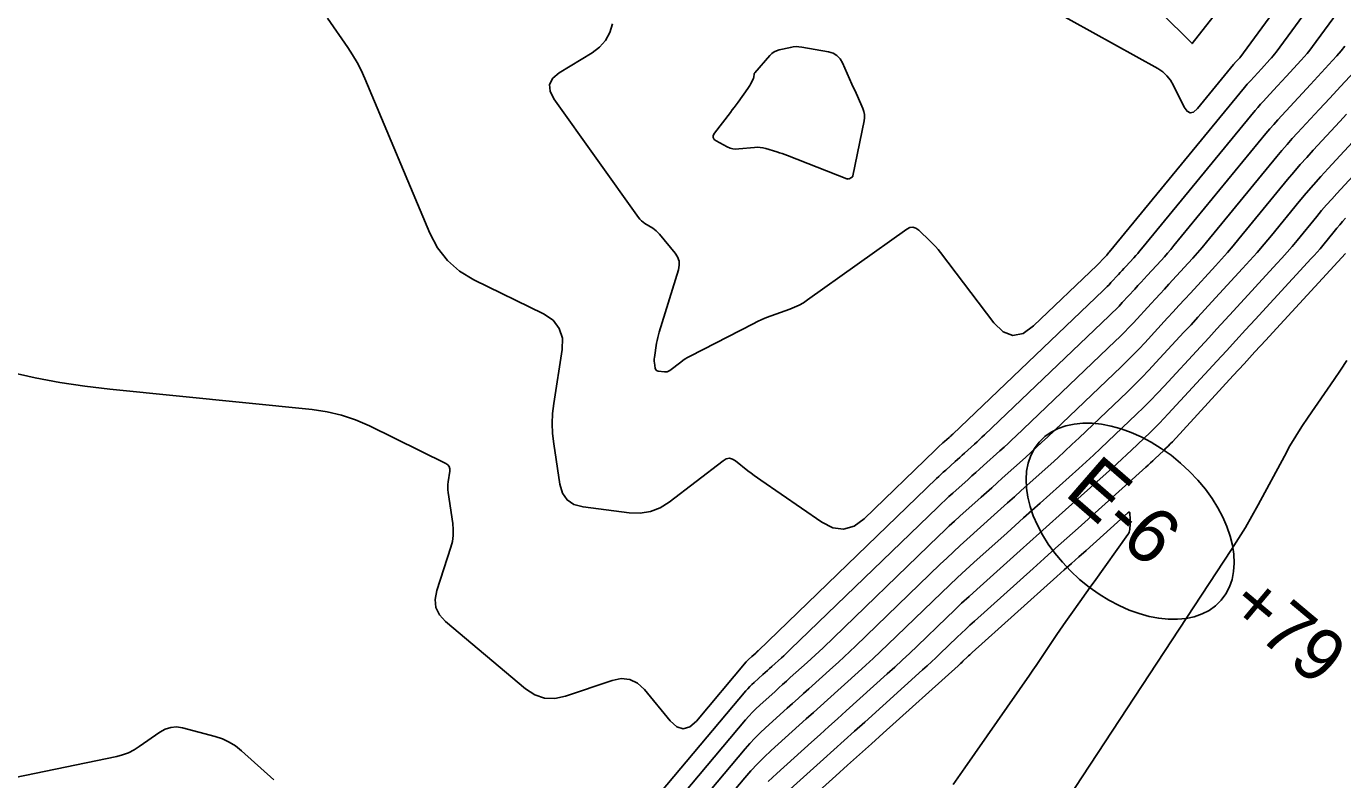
# Model space of a CAD drawing. Extents: x 1005228 to 1008882, y 1883389 to 1885754.
# Drawn here: x 1007592.2 to 1007741.8, y 1884616.1 to 1884701.7 of the extents above; entities that cross this region are included whole.
import ezdxf

# ---------------------------------------------------------------- set-up
doc = ezdxf.new("R2010")
doc.units = 0
for name, color, linetype in [('C-ANNO-NOTE', 7, 'Continuous'), ('R_Erosion', 7, 'Continuous'), ('S_BASELINE', 7, 'Continuous'), ('S_BRIDGE', 7, 'Continuous')]:
    doc.layers.add(name, color=color, linetype=linetype)

msp = doc.modelspace()

# ---------------------------------------------------------------- linework, layer by layer
at = {"layer": 'C-ANNO-NOTE'}
for points in [[(1007744.79, 1884718.15), (1007730.07, 1884698.09), (1007730.04, 1884698.04), (1007730, 1884698), (1007729.97, 1884697.96), (1007729.93, 1884697.92), (1007729.5, 1884697.46), (1007729.47, 1884697.42), (1007729.43, 1884697.38), (1007729.4, 1884697.34), (1007729.37, 1884697.31), (1007725.26, 1884692.31), (1007724.84, 1884691.92), (1007724.45, 1884691.82), (1007724.1, 1884692), (1007723.78, 1884692.48), (1007722.56, 1884694.95), (1007722.22, 1884695.54), (1007721.81, 1884696.05), (1007721.32, 1884696.49), (1007720.75, 1884696.86), (1007706, 1884705.08)], [(1007658.79, 1884701.95), (1007658.47, 1884700.94), (1007657.98, 1884700.06), (1007657.31, 1884699.3), (1007656.47, 1884698.66), (1007652.73, 1884696.36), (1007652, 1884695.75), (1007651.65, 1884695.06), (1007651.7, 1884694.28), (1007652.14, 1884693.43), (1007661.75, 1884679.94), (1007661.9, 1884679.74), (1007662.08, 1884679.56), (1007662.27, 1884679.4), (1007662.48, 1884679.25), (1007663.36, 1884678.71), (1007663.57, 1884678.56), (1007663.77, 1884678.4), (1007663.95, 1884678.23), (1007664.12, 1884678.04), (1007665.91, 1884675.89), (1007666.19, 1884675.45), (1007666.35, 1884674.99), (1007666.38, 1884674.5), (1007666.28, 1884673.98), (1007664.1, 1884666.9), (1007664.01, 1884666.59), (1007663.93, 1884666.28), (1007663.86, 1884665.96), (1007663.81, 1884665.64), (1007663.56, 1884664.03), (1007663.54, 1884663.88), (1007663.54, 1884663.73), (1007663.54, 1884663.58), (1007663.56, 1884663.42), (1007663.65, 1884662.82), (1007663.69, 1884662.69), (1007663.76, 1884662.59), (1007663.86, 1884662.52), (1007664, 1884662.48), (1007664.69, 1884662.39), (1007664.85, 1884662.39), (1007665, 1884662.41), (1007665.15, 1884662.47), (1007665.29, 1884662.55), (1007666.54, 1884663.51), (1007666.79, 1884663.7), (1007667.06, 1884663.88), (1007667.33, 1884664.04), (1007667.61, 1884664.19), (1007674.76, 1884667.86), (1007675.27, 1884668.11), (1007675.78, 1884668.34), (1007676.31, 1884668.56), (1007676.83, 1884668.76), (1007678.96, 1884669.52), (1007679.49, 1884669.73), (1007679.99, 1884669.97), (1007680.48, 1884670.25), (1007680.95, 1884670.56), (1007692.24, 1884678.6), (1007692.6, 1884678.79), (1007692.94, 1884678.83), (1007693.28, 1884678.74), (1007693.6, 1884678.5), (1007694.88, 1884677.26), (1007695.2, 1884676.95), (1007695.5, 1884676.62), (1007695.79, 1884676.29), (1007696.06, 1884675.94), (1007702.14, 1884667.98), (1007703.19, 1884666.94), (1007704.3, 1884666.54), (1007705.45, 1884666.77), (1007706.65, 1884667.62), (1007713.89, 1884674.52), (1007713.95, 1884674.59), (1007714.02, 1884674.66), (1007714.09, 1884674.73), (1007714.15, 1884674.8), (1007714.48, 1884675.15), (1007714.67, 1884675.36), (1007714.96, 1884675.67), (1007715.03, 1884675.75), (1007715.09, 1884675.82), (1007715.16, 1884675.9), (1007715.23, 1884675.98), (1007730.6, 1884694.69), (1007730.77, 1884694.89), (1007730.94, 1884695.09), (1007731.11, 1884695.29), (1007731.29, 1884695.48), (1007732.54, 1884696.83), (1007733.5, 1884697.87), (1007733.68, 1884698.07), (1007733.86, 1884698.29), (1007734.04, 1884698.5), (1007734.21, 1884698.73), (1007746.98, 1884716.13)], [(1007742.04, 1884699.42), (1007741.59, 1884698.86), (1007741.12, 1884698.3), (1007740.63, 1884697.76), (1007738.13, 1884695.06), (1007737.2, 1884694.05), (1007734.86, 1884691.54), (1007734.4, 1884691.03), (1007733.95, 1884690.52), (1007733.5, 1884689.99), (1007733.06, 1884689.47), (1007722.6, 1884676.74), (1007722.24, 1884676.31), (1007721.88, 1884675.88), (1007721.51, 1884675.46), (1007721.13, 1884675.05), (1007719.57, 1884673.35), (1007719.22, 1884672.97), (1007718.86, 1884672.58), (1007718.5, 1884672.19), (1007718.14, 1884671.8), (1007716.72, 1884670.26), (1007716.36, 1884669.87), (1007715.99, 1884669.49), (1007715.62, 1884669.12), (1007715.24, 1884668.75), (1007701.06, 1884655.22), (1007700.78, 1884654.96), (1007700.51, 1884654.7), (1007700.23, 1884654.44), (1007699.95, 1884654.19), (1007698.79, 1884653.15), (1007698.52, 1884652.91), (1007698.26, 1884652.67), (1007697.99, 1884652.44), (1007697.72, 1884652.2), (1007696.66, 1884651.24), (1007696.39, 1884651), (1007696.13, 1884650.76), (1007695.87, 1884650.51), (1007695.61, 1884650.26), (1007675.35, 1884630.71), (1007675.28, 1884630.64), (1007675.21, 1884630.57), (1007675.14, 1884630.51), (1007675.07, 1884630.44), (1007674.64, 1884630.06), (1007674.24, 1884629.69), (1007674.17, 1884629.63), (1007674.11, 1884629.57), (1007674.04, 1884629.5), (1007673.98, 1884629.43), (1007668.33, 1884622.71), (1007667.59, 1884622.04), (1007666.84, 1884621.82), (1007666.1, 1884622.05), (1007665.36, 1884622.72), (1007662.41, 1884626.3), (1007661.63, 1884627.03), (1007660.76, 1884627.45), (1007659.79, 1884627.55), (1007658.74, 1884627.33), (1007653.44, 1884625.53), (1007652.22, 1884625.26), (1007651.06, 1884625.31), (1007649.96, 1884625.68), (1007648.92, 1884626.37), (1007639.81, 1884634.03), (1007639.12, 1884634.77), (1007638.72, 1884635.61), (1007638.62, 1884636.52), (1007638.81, 1884637.53), (1007640.41, 1884642.46), (1007640.59, 1884643.13), (1007640.68, 1884643.8), (1007640.7, 1884644.48), (1007640.63, 1884645.17), (1007640.1, 1884648.7), (1007640.07, 1884649), (1007640.06, 1884649.3), (1007640.07, 1884649.6), (1007640.11, 1884649.91), (1007640.29, 1884651.11), (1007640.3, 1884651.39), (1007640.22, 1884651.63), (1007640.07, 1884651.83), (1007639.84, 1884651.99), (1007631.16, 1884656.25), (1007629.6, 1884656.93), (1007628, 1884657.47), (1007626.35, 1884657.86), (1007624.67, 1884658.1), (1007601.68, 1884660.41), (1007598.82, 1884660.75), (1007595.98, 1884661.19), (1007593.16, 1884661.73), (1007590.35, 1884662.37)], [(1007657.59, 1884606.68), (1007673.94, 1884626.14), (1007674.17, 1884626.39), (1007674.4, 1884626.64), (1007674.63, 1884626.88), (1007674.88, 1884627.11), (1007675.88, 1884628.01), (1007676.14, 1884628.24), (1007676.39, 1884628.46), (1007676.64, 1884628.69), (1007676.89, 1884628.92), (1007677.98, 1884629.9), (1007678.25, 1884630.14), (1007678.51, 1884630.39), (1007678.77, 1884630.63), (1007679.03, 1884630.88), (1007695.75, 1884647.02), (1007696.17, 1884647.42), (1007696.6, 1884647.82), (1007697.03, 1884648.22), (1007697.46, 1884648.61), (1007699.2, 1884650.17), (1007699.64, 1884650.56), (1007700.07, 1884650.95), (1007700.51, 1884651.34), (1007700.94, 1884651.74), (1007702.83, 1884653.43), (1007703.29, 1884653.84), (1007703.74, 1884654.26), (1007704.19, 1884654.68), (1007704.64, 1884655.1), (1007715.92, 1884665.87), (1007716.45, 1884666.38), (1007716.98, 1884666.91), (1007717.49, 1884667.44), (1007718, 1884667.98), (1007720.01, 1884670.17), (1007720.51, 1884670.71), (1007721.02, 1884671.26), (1007721.52, 1884671.8), (1007722.02, 1884672.35), (1007724.22, 1884674.74), (1007724.75, 1884675.32), (1007725.27, 1884675.91), (1007725.79, 1884676.51), (1007726.29, 1884677.12), (1007734.29, 1884686.86), (1007734.87, 1884687.54), (1007735.45, 1884688.23), (1007736.05, 1884688.9), (1007736.65, 1884689.56), (1007739.09, 1884692.2), (1007740.31, 1884693.51), (1007741.54, 1884694.83), (1007744.2, 1884697.71)], [(1007742.21, 1884691.66), (1007741.46, 1884690.84), (1007738.44, 1884687.59), (1007737.69, 1884686.77), (1007736.96, 1884685.94), (1007736.23, 1884685.09), (1007735.52, 1884684.24), (1007729.98, 1884677.5), (1007729.33, 1884676.71), (1007728.67, 1884675.94), (1007727.99, 1884675.18), (1007727.31, 1884674.43), (1007724.47, 1884671.34), (1007723.82, 1884670.64), (1007723.17, 1884669.94), (1007722.52, 1884669.23), (1007721.88, 1884668.53), (1007719.28, 1884665.71), (1007718.63, 1884665.01), (1007717.96, 1884664.33), (1007717.29, 1884663.65), (1007716.6, 1884662.98), (1007708.22, 1884654.99), (1007707.6, 1884654.4), (1007706.98, 1884653.82), (1007706.35, 1884653.24), (1007705.71, 1884652.66), (1007703.09, 1884650.32), (1007702.49, 1884649.78), (1007701.89, 1884649.23), (1007701.28, 1884648.69), (1007700.68, 1884648.15), (1007698.26, 1884645.98), (1007697.66, 1884645.44), (1007697.07, 1884644.89), (1007696.47, 1884644.33), (1007695.89, 1884643.77), (1007682.72, 1884631.05), (1007682.27, 1884630.63), (1007681.81, 1884630.2), (1007681.36, 1884629.78), (1007680.9, 1884629.36), (1007679, 1884627.65), (1007678.57, 1884627.26), (1007678.13, 1884626.87), (1007677.7, 1884626.48), (1007677.26, 1884626.09), (1007675.53, 1884624.52), (1007675.1, 1884624.12), (1007674.69, 1884623.71), (1007674.29, 1884623.28), (1007673.9, 1884622.84), (1007660.65, 1884607.07)], [(1007743.82, 1884689.49), (1007740.13, 1884685.51), (1007739.29, 1884684.58), (1007738.46, 1884683.65), (1007737.64, 1884682.7), (1007736.84, 1884681.74), (1007733.67, 1884677.87), (1007732.87, 1884676.92), (1007732.06, 1884675.97), (1007731.23, 1884675.04), (1007730.4, 1884674.12), (1007726.92, 1884670.34), (1007726.12, 1884669.48), (1007725.33, 1884668.62), (1007724.54, 1884667.75), (1007723.74, 1884666.89), (1007720.56, 1884663.44), (1007719.76, 1884662.58), (1007718.95, 1884661.74), (1007718.12, 1884660.91), (1007717.28, 1884660.1), (1007711.81, 1884654.88), (1007711.01, 1884654.12), (1007710.21, 1884653.38), (1007709.41, 1884652.64), (1007708.59, 1884651.9), (1007705.25, 1884648.9), (1007704.47, 1884648.21), (1007703.7, 1884647.51), (1007702.93, 1884646.82), (1007702.16, 1884646.13), (1007699.07, 1884643.35), (1007698.3, 1884642.66), (1007697.53, 1884641.95), (1007696.78, 1884641.24), (1007696.03, 1884640.53), (1007686.4, 1884631.23), (1007685.76, 1884630.62), (1007685.12, 1884630.01), (1007684.47, 1884629.42), (1007683.82, 1884628.82), (1007681.12, 1884626.39), (1007680.5, 1884625.83), (1007679.88, 1884625.28), (1007679.26, 1884624.72), (1007678.64, 1884624.16), (1007676.17, 1884621.94), (1007675.56, 1884621.37), (1007674.98, 1884620.78), (1007674.41, 1884620.17), (1007673.86, 1884619.55), (1007663.7, 1884607.46)], [(1007742.11, 1884679.84), (1007741.77, 1884679.47), (1007741.44, 1884679.09), (1007741.11, 1884678.71), (1007740.79, 1884678.33), (1007739.52, 1884676.77), (1007739.2, 1884676.39), (1007738.87, 1884676.01), (1007738.54, 1884675.63), (1007738.2, 1884675.26), (1007731.82, 1884668.33), (1007730.73, 1884667.15), (1007729.64, 1884665.97), (1007728.56, 1884664.79), (1007727.47, 1884663.61), (1007721.95, 1884657.62), (1007721.45, 1884657.08), (1007720.94, 1884656.56), (1007720.42, 1884656.04), (1007719.89, 1884655.52), (1007717.76, 1884653.49), (1007717.23, 1884652.99), (1007716.69, 1884652.49), (1007716.15, 1884651.99), (1007715.6, 1884651.5), (1007709.55, 1884646.06), (1007708.44, 1884645.07), (1007707.33, 1884644.07), (1007706.22, 1884643.08), (1007705.11, 1884642.08), (1007700.19, 1884637.67), (1007699.32, 1884636.88), (1007698.47, 1884636.09), (1007697.62, 1884635.29), (1007696.77, 1884634.49), (1007693.42, 1884631.24), (1007692.57, 1884630.44), (1007691.72, 1884629.64), (1007690.87, 1884628.85), (1007690, 1884628.06), (1007685.34, 1884623.87), (1007684.36, 1884622.98), (1007683.37, 1884622.09), (1007682.39, 1884621.2), (1007681.4, 1884620.31), (1007677.46, 1884616.76), (1007676.49, 1884615.86)], [(1007677.08, 1884613.26), (1007682.78, 1884618.39), (1007683.95, 1884619.44), (1007685.12, 1884620.5), (1007686.29, 1884621.55), (1007687.46, 1884622.6), (1007694.04, 1884628.53), (1007694.54, 1884628.99), (1007695.03, 1884629.44), (1007695.53, 1884629.9), (1007696.01, 1884630.37), (1007697.95, 1884632.24), (1007698.44, 1884632.71), (1007698.93, 1884633.17), (1007699.42, 1884633.62), (1007699.92, 1884634.08), (1007706.59, 1884640.06), (1007707.86, 1884641.2), (1007709.14, 1884642.35), (1007710.42, 1884643.5), (1007711.7, 1884644.64), (1007719.42, 1884651.57), (1007719.68, 1884651.8), (1007719.93, 1884652.04), (1007720.19, 1884652.27), (1007720.44, 1884652.51), (1007721.44, 1884653.47), (1007721.69, 1884653.71), (1007721.94, 1884653.96), (1007722.18, 1884654.21), (1007722.42, 1884654.46), (1007729.34, 1884661.98), (1007730.57, 1884663.31), (1007731.8, 1884664.65), (1007733.03, 1884665.99), (1007734.27, 1884667.33), (1007742.1, 1884675.84)], [(1007742.26, 1884663.67), (1007741.54, 1884662.6), (1007740.8, 1884661.53), (1007737.85, 1884657.26), (1007737.13, 1884656.18), (1007736.44, 1884655.08), (1007735.78, 1884653.97), (1007735.15, 1884652.83), (1007732.17, 1884647.3), (1007731.46, 1884646), (1007730.72, 1884644.72), (1007729.94, 1884643.46), (1007729.15, 1884642.22), (1007710.49, 1884613.85)], [(1007676.64, 1884609.69), (1007684.16, 1884616.47), (1007685.51, 1884617.69), (1007686.87, 1884618.9), (1007688.22, 1884620.12), (1007689.57, 1884621.34), (1007698.08, 1884629), (1007698.21, 1884629.13), (1007698.35, 1884629.25), (1007698.48, 1884629.37), (1007698.61, 1884629.5), (1007699.12, 1884630), (1007699.26, 1884630.12), (1007699.39, 1884630.24), (1007699.52, 1884630.37), (1007699.65, 1884630.49), (1007709.3, 1884639.14), (1007710.13, 1884639.89), (1007710.96, 1884640.63), (1007711.78, 1884641.37), (1007712.61, 1884642.11), (1007717.36, 1884646.38), (1007717.46, 1884646.44), (1007717.53, 1884646.45), (1007717.57, 1884646.4), (1007717.59, 1884646.28), (1007717.62, 1884645.71), (1007717.62, 1884645.57), (1007717.62, 1884645.42), (1007717.62, 1884645.28), (1007717.62, 1884645.14), (1007717.58, 1884644.49), (1007717.56, 1884644.33), (1007717.52, 1884644.19), (1007717.46, 1884644.05), (1007717.37, 1884643.92), (1007713.52, 1884638.53), (1007713.17, 1884638.03), (1007712.81, 1884637.53), (1007712.45, 1884637.03), (1007712.1, 1884636.54), (1007710.68, 1884634.54), (1007710.32, 1884634.04), (1007709.97, 1884633.54), (1007709.63, 1884633.04), (1007709.29, 1884632.53), (1007707.7, 1884630.16), (1007707.33, 1884629.6), (1007706.95, 1884629.04), (1007706.56, 1884628.48), (1007706.17, 1884627.92), (1007698.83, 1884617.4), (1007697.52, 1884615.51)], [(1007579.12, 1884613.89), (1007602.44, 1884618.7), (1007603.12, 1884618.87), (1007603.78, 1884619.12), (1007604.41, 1884619.43), (1007605.01, 1884619.81), (1007607.36, 1884621.46), (1007607.96, 1884621.8), (1007608.59, 1884621.99), (1007609.24, 1884622.04), (1007609.92, 1884621.93), (1007613.63, 1884620.96), (1007614.46, 1884620.69), (1007615.23, 1884620.33), (1007615.96, 1884619.88), (1007616.63, 1884619.34), (1007620.31, 1884616.03)]]:
    msp.add_lwpolyline(points, dxfattribs=at)
msp.add_lwpolyline([(1007672.82, 1884687.71), (1007672.48, 1884687.75), (1007672.15, 1884687.83), (1007671.83, 1884687.97), (1007670.58, 1884688.64), (1007670.33, 1884688.81), (1007670.22, 1884689.02), (1007670.24, 1884689.26), (1007670.39, 1884689.53), (1007672.19, 1884691.86), (1007672.41, 1884692.15), (1007672.63, 1884692.44), (1007672.84, 1884692.73), (1007673.06, 1884693.03), (1007674.16, 1884694.59), (1007674.24, 1884694.7), (1007674.32, 1884694.83), (1007674.39, 1884694.95), (1007674.46, 1884695.07), (1007674.8, 1884695.73), (1007674.82, 1884695.79), (1007674.84, 1884695.84), (1007674.85, 1884695.89), (1007674.86, 1884695.95), (1007674.88, 1884696.17), (1007674.89, 1884696.22), (1007674.9, 1884696.28), (1007674.93, 1884696.32), (1007674.96, 1884696.37), (1007676.68, 1884698.34), (1007676.9, 1884698.56), (1007677.16, 1884698.74), (1007677.44, 1884698.88), (1007677.74, 1884698.97), (1007679.02, 1884699.27), (1007679.34, 1884699.32), (1007679.66, 1884699.35), (1007679.98, 1884699.34), (1007680.3, 1884699.3), (1007683.34, 1884698.74), (1007683.86, 1884698.59), (1007684.3, 1884698.33), (1007684.65, 1884697.97), (1007684.92, 1884697.5), (1007686.01, 1884695.08), (1007686.16, 1884694.74), (1007686.32, 1884694.4), (1007686.47, 1884694.05), (1007686.62, 1884693.71), (1007687.23, 1884692.33), (1007687.35, 1884691.98), (1007687.42, 1884691.63), (1007687.43, 1884691.27), (1007687.38, 1884690.9), (1007686.11, 1884684.68), (1007686.09, 1884684.61), (1007686.05, 1884684.56), (1007686.01, 1884684.51), (1007685.95, 1884684.47), (1007685.69, 1884684.34), (1007685.63, 1884684.31), (1007685.56, 1884684.3), (1007685.49, 1884684.31), (1007685.43, 1884684.32), (1007678.69, 1884686.97), (1007678.38, 1884687.09), (1007678.07, 1884687.2), (1007677.76, 1884687.3), (1007677.45, 1884687.4), (1007676.2, 1884687.77), (1007675.88, 1884687.85), (1007675.56, 1884687.9), (1007675.24, 1884687.91), (1007674.92, 1884687.89), (1007673.16, 1884687.72)], close=True, dxfattribs=at)
at = {"layer": 'R_Erosion'}
msp.add_lwpolyline([(1007479.35, 1884649.35), (1007490.06, 1884659.98), (1007582.04, 1884767.38), (1007608.23, 1884786.44), (1007622.73, 1884788.72), (1007640.54, 1884783.01), (1007724.67, 1884699.7), (1007740.7, 1884720.15)], dxfattribs=at)
msp.add_ellipse((1007717.62, 1884645.42), major_axis=(10.34, -8.98), ratio=0.638788, dxfattribs=at)
at = {"layer": 'S_BRIDGE'}
for points in [[(1007749.17, 1884714.12), (1007738.35, 1884699.36), (1007738.04, 1884698.96), (1007737.73, 1884698.57), (1007737.4, 1884698.19), (1007737.07, 1884697.81), (1007735.34, 1884695.95), (1007734.37, 1884694.9), (1007733.08, 1884693.51), (1007732.76, 1884693.16), (1007732.44, 1884692.8), (1007732.13, 1884692.44), (1007731.83, 1884692.08), (1007718.91, 1884676.36), (1007718.7, 1884676.1), (1007718.49, 1884675.85), (1007718.27, 1884675.6), (1007718.05, 1884675.36), (1007717.12, 1884674.36), (1007716.91, 1884674.13), (1007716.7, 1884673.9), (1007716.49, 1884673.67), (1007716.28, 1884673.44), (1007715.44, 1884672.53), (1007715.22, 1884672.3), (1007715.01, 1884672.08), (1007714.79, 1884671.86), (1007714.56, 1884671.64), (1007697.47, 1884655.33), (1007697.37, 1884655.24), (1007697.27, 1884655.14), (1007697.17, 1884655.05), (1007697.07, 1884654.95), (1007696.54, 1884654.48), (1007696.35, 1884654.31), (1007695.86, 1884653.87), (1007695.76, 1884653.78), (1007695.66, 1884653.69), (1007695.56, 1884653.6), (1007695.47, 1884653.51), (1007687.38, 1884645.7), (1007686.24, 1884644.86), (1007685.06, 1884644.52), (1007683.84, 1884644.67), (1007682.58, 1884645.3), (1007675.64, 1884650.09), (1007675.27, 1884650.35), (1007674.91, 1884650.61), (1007674.55, 1884650.88), (1007674.19, 1884651.16), (1007672.78, 1884652.28), (1007672.43, 1884652.49), (1007672.08, 1884652.57), (1007671.72, 1884652.5), (1007671.36, 1884652.3), (1007665.24, 1884647.59), (1007664.2, 1884646.93), (1007663.1, 1884646.51), (1007661.93, 1884646.32), (1007660.7, 1884646.37), (1007655.44, 1884647.05), (1007654.41, 1884647.33), (1007653.63, 1884647.85), (1007653.09, 1884648.62), (1007652.8, 1884649.64), (1007652.11, 1884654.22), (1007651.98, 1884655.37), (1007651.94, 1884656.51), (1007651.98, 1884657.66), (1007652.11, 1884658.8), (1007653.06, 1884664.92), (1007653.09, 1884666.22), (1007652.74, 1884667.33), (1007652.03, 1884668.25), (1007650.94, 1884668.97), (1007643.03, 1884672.86), (1007641.41, 1884673.83), (1007640.04, 1884675.04), (1007638.91, 1884676.48), (1007638.04, 1884678.15), (1007630.64, 1884695.74), (1007630.22, 1884696.66), (1007629.76, 1884697.55), (1007629.25, 1884698.42), (1007628.7, 1884699.27), (1007626.4, 1884702.6)], [(1007746.18, 1884688.14), (1007741.12, 1884682.67), (1007740.53, 1884682.03), (1007739.95, 1884681.37), (1007739.38, 1884680.71), (1007738.82, 1884680.03), (1007736.59, 1884677.33), (1007736.03, 1884676.65), (1007735.46, 1884675.99), (1007734.88, 1884675.33), (1007734.3, 1884674.69), (1007729.37, 1884669.34), (1007728.43, 1884668.32), (1007727.49, 1884667.29), (1007726.55, 1884666.27), (1007725.61, 1884665.25), (1007721.49, 1884660.78), (1007720.72, 1884659.96), (1007719.94, 1884659.15), (1007719.15, 1884658.36), (1007718.34, 1884657.58), (1007715.09, 1884654.47), (1007714.27, 1884653.7), (1007713.45, 1884652.93), (1007712.62, 1884652.17), (1007711.79, 1884651.42), (1007707.4, 1884647.48), (1007706.46, 1884646.64), (1007705.51, 1884645.79), (1007704.57, 1884644.95), (1007703.63, 1884644.1), (1007699.87, 1884640.73), (1007698.93, 1884639.88), (1007698, 1884639.02), (1007697.08, 1884638.16), (1007696.17, 1884637.28), (1007690.08, 1884631.4), (1007689.25, 1884630.61), (1007688.42, 1884629.83), (1007687.58, 1884629.05), (1007686.73, 1884628.28), (1007683.23, 1884625.13), (1007682.43, 1884624.41), (1007681.63, 1884623.68), (1007680.82, 1884622.96), (1007680.02, 1884622.24), (1007676.82, 1884619.35), (1007676.03, 1884618.61), (1007675.27, 1884617.85), (1007674.53, 1884617.07), (1007673.82, 1884616.25), (1007666.76, 1884607.85)]]:
    msp.add_lwpolyline(points, dxfattribs=at)

# ---------------------------------------------------------------- texts
at = {"layer": 'R_Erosion'}
msp.add_text('E-6', height=6.25, rotation=319.0118, dxfattribs=at).set_placement((1007710.02, 1884648.5))
at = {"layer": 'S_BASELINE'}
msp.add_text('+79', height=6, rotation=320, dxfattribs=at).set_placement((1007728.44, 1884635.26))

doc.saveas('drawing.dxf')
